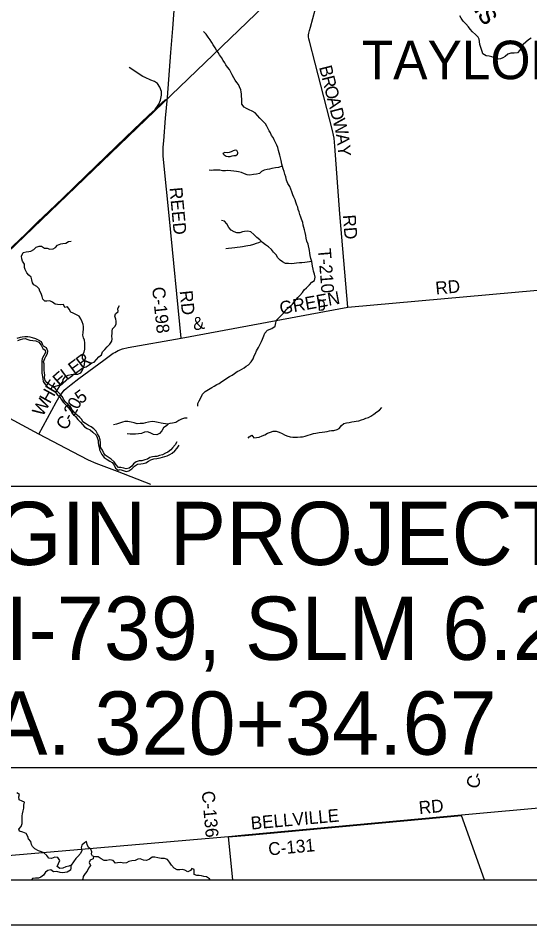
# Model space of a CAD drawing. Extents: x 0 to 34, y 0 to 22.
# Drawn here: x 5.532 to 6.665, y 14 to 16.008 of the extents above; entities that cross this region are included whole.
import ezdxf

# ---------------------------------------------------------------- set-up
doc = ezdxf.new("R2010")
doc.units = 0
for name, color, linetype in [('GM_X_Corporation', 7, 'Continuous'), ('GM_X_County_Road', 7, 'Continuous'), ('GM_X_County_Road_Text', 7, 'Continuous'), ('GM_X_Minor_Lake', 7, 'Continuous'), ('GM_X_Minor_River', 7, 'Continuous'), ('GM_X_Minor_River_Text', 7, 'Continuous'), ('GM_X_Rail_Line', 7, 'Continuous'), ('GM_X_Township_Road', 7, 'Continuous'), ('GM_X_Township_Road_Text', 7, 'Continuous'), ('GM_X_Township_Text', 7, 'Continuous'), ('SH_Data', 7, 'Continuous'), ('SH_Text', 7, 'Continuous')]:
    doc.layers.add(name, color=color, linetype=linetype)

msp = doc.modelspace()

# ---------------------------------------------------------------- linework, layer by layer
at = {"layer": 'GM_X_Corporation'}
msp.add_lwpolyline([(2.7052, 14.1), (8.9, 14.1), (8.9, 20.9), (3.3687, 20.9)], dxfattribs=at)
msp.add_lwpolyline([(5.0367, 14.1), (8.579, 14.1), (8.5781, 14.1185), (8.5553, 14.4065), (8.4217, 14.3956), (8.2117, 14.3797), (8.0986, 14.3711), (7.9912, 14.363), (7.8543, 14.3535), (7.661, 14.3447), (7.5929, 14.3405), (7.4631, 14.3291), (7.1407, 14.2995), (6.5134, 14.2426), (6.0344, 14.1984), (5.9982, 14.195), (5.4229, 14.1455), (5.0357, 14.1114)], close=True, dxfattribs=at)
at = {"layer": 'GM_X_County_Road'}
for p, q in [((6.5647, 14.1), (6.5135, 14.2423)), ((6.0076, 14.1), (5.9983, 14.1947))]:
    msp.add_line(p, q, dxfattribs=at)
for points in [[(5.8932, 15.2994), (5.8674, 15.5635), (5.855, 15.6874), (5.8535, 15.703), (5.8532, 15.7217), (5.8547, 15.7358), (5.8584, 15.7865), (5.8627, 15.8321), (5.8703, 15.9318), (5.8747, 15.985), (5.8831, 16.0962)], [(5.746, 15.2677), (5.7539, 15.2718), (5.7631, 15.2753), (5.7762, 15.2782), (5.8932, 15.2994), (6.2619, 15.3675), (6.888, 15.4237)], [(5.5784, 15.0868), (5.6166, 15.1573), (5.6223, 15.1676), (5.6342, 15.1836), (5.6386, 15.1878), (5.6496, 15.1967), (5.6669, 15.2098), (5.7217, 15.2506), (5.7425, 15.2659), (5.746, 15.2677)], [(5.826, 14.9751), (5.7525, 15.0039), (5.7051, 15.0219), (5.6884, 15.0289), (5.6697, 15.0384), (5.5784, 15.0868), (5.4856, 15.1361)], [(5.9983, 14.1947), (6.0345, 14.1981), (6.5135, 14.2423)]]:
    msp.add_lwpolyline(points, dxfattribs=at)
at = {"layer": 'GM_X_Minor_Lake'}
for points in [[(6.0184, 15.709), (6.0188, 15.7104), (6.0165, 15.7146), (6.0125, 15.7156), (6.008, 15.7139), (6.0036, 15.712), (5.9996, 15.7103), (5.9947, 15.7094), (5.9902, 15.7099), (5.9851, 15.7079)], [(5.9851, 15.7079), (5.9886, 15.7048), (5.9928, 15.7018), (5.9975, 15.701), (6.0013, 15.7016), (6.0057, 15.7027), (6.0098, 15.7032), (6.014, 15.7032), (6.0176, 15.7064), (6.0184, 15.709)], [(6.1979, 15.3842), (6.1989, 15.3785), (6.1987, 15.3736), (6.1986, 15.3694), (6.1984, 15.3652), (6.1988, 15.3614), (6.2034, 15.3616), (6.2073, 15.362), (6.2092, 15.3637)], [(6.2092, 15.3637), (6.2104, 15.3648), (6.2106, 15.3695), (6.2104, 15.3739), (6.2095, 15.3783), (6.2061, 15.3819), (6.2017, 15.3829), (6.1979, 15.3842)]]:
    msp.add_lwpolyline(points, dxfattribs=at)
at = {"layer": 'GM_X_Minor_River'}
for points in [[(6.5566, 15.943), (6.5544, 15.9494), (6.5537, 15.9563), (6.5529, 15.961), (6.5503, 15.9659), (6.5446, 15.9717), (6.5382, 15.977), (6.5327, 15.9835), (6.5292, 15.9884), (6.5233, 15.9953), (6.5173, 16.0013), (6.5128, 16.0076), (6.5103, 16.0129)], [(6.1087, 15.7144), (6.1074, 15.7212), (6.1053, 15.7262), (6.1029, 15.7311), (6.0991, 15.7384), (6.0965, 15.7431), (6.0935, 15.7481), (6.0911, 15.7534), (6.0883, 15.7583), (6.0849, 15.7639), (6.0828, 15.7686), (6.08, 15.7734), (6.074, 15.7797), (6.0674, 15.786), (6.0621, 15.7922), (6.0567, 15.7981), (6.0504, 15.802), (6.0438, 15.805), (6.0376, 15.8075), (6.0325, 15.8102), (6.0276, 15.8169), (6.0273, 15.8235), (6.0271, 15.8292), (6.0268, 15.8343), (6.0266, 15.8395), (6.0262, 15.8444), (6.0249, 15.8492), (6.0221, 15.8558), (6.0199, 15.8607), (6.0165, 15.8655), (6.0126, 15.8707), (6.0097, 15.8754), (6.0062, 15.8823), (6.003, 15.888), (5.9998, 15.8939), (5.9961, 15.8992), (5.9923, 15.904), (5.9895, 15.9089), (5.9863, 15.914), (5.9823, 15.9203), (5.978, 15.9268), (5.9748, 15.9315), (5.9716, 15.9367), (5.9683, 15.9416), (5.9641, 15.9485), (5.9613, 15.9534), (5.9572, 15.9599), (5.953, 15.9652), (5.9482, 15.9721), (5.9429, 15.9784)], [(6.6679, 15.9632), (6.662, 15.9595), (6.6559, 15.9542), (6.6502, 15.9496), (6.6462, 15.9428), (6.6426, 15.9366), (6.6373, 15.9309), (6.6303, 15.93), (6.6229, 15.9304), (6.6164, 15.9278), (6.61, 15.923), (6.605, 15.92), (6.5997, 15.9174), (6.595, 15.9168), (6.5882, 15.9193), (6.5812, 15.9222), (6.5747, 15.9234), (6.5681, 15.9243), (6.5611, 15.9285), (6.5591, 15.9335), (6.5579, 15.9382), (6.5566, 15.943)], [(5.9297, 15.1483), (5.9298, 15.1542), (5.9328, 15.1606), (5.9366, 15.1669), (5.9405, 15.1752), (5.9466, 15.181), (5.9538, 15.1854), (5.961, 15.1901), (5.9661, 15.1931), (5.9718, 15.1965), (5.977, 15.1989), (5.9831, 15.2034), (5.9889, 15.2066), (5.9945, 15.2104), (6, 15.2143), (6.0059, 15.2173), (6.0114, 15.2207), (6.0169, 15.2251), (6.0224, 15.2273), (6.0271, 15.2301), (6.0323, 15.2337), (6.0372, 15.2369), (6.0423, 15.2401), (6.048, 15.2465), (6.0523, 15.2535), (6.0551, 15.2599), (6.0574, 15.2651), (6.0601, 15.2707), (6.0645, 15.2783), (6.0672, 15.2842), (6.0712, 15.2914), (6.0729, 15.2968), (6.076, 15.3039), (6.0787, 15.3101), (6.0846, 15.3169), (6.0941, 15.3206), (6.1013, 15.3255), (6.1029, 15.3329), (6.104, 15.3388), (6.1086, 15.3437), (6.1143, 15.3494), (6.121, 15.3562), (6.1255, 15.3618), (6.1322, 15.3677), (6.1394, 15.3745), (6.1448, 15.3807), (6.1511, 15.3888), (6.156, 15.3937), (6.1615, 15.4005), (6.1657, 15.406), (6.1705, 15.4107), (6.177, 15.4175), (6.1821, 15.423), (6.1886, 15.4271), (6.1901, 15.4342), (6.1883, 15.441), (6.1864, 15.4471), (6.1851, 15.452), (6.184, 15.4587), (6.1831, 15.464), (6.1824, 15.4687), (6.1805, 15.4756), (6.179, 15.482), (6.1781, 15.4872), (6.177, 15.4932), (6.174, 15.5069), (6.1714, 15.5137), (6.1697, 15.5202), (6.169, 15.5267), (6.1679, 15.5329), (6.1662, 15.539), (6.165, 15.5441), (6.1633, 15.5496), (6.1622, 15.555), (6.1596, 15.5626), (6.1581, 15.5673), (6.1562, 15.5728), (6.1541, 15.5785), (6.1523, 15.5839), (6.1512, 15.5888), (6.1491, 15.5939), (6.1471, 15.6004), (6.1456, 15.6055), (6.1428, 15.6114), (6.1407, 15.6165), (6.1379, 15.623), (6.136, 15.6287), (6.1336, 15.6348), (6.1295, 15.6416), (6.1267, 15.6489), (6.1246, 15.6561), (6.1228, 15.6622), (6.1211, 15.6681), (6.1191, 15.6743), (6.1172, 15.6795), (6.1159, 15.6842), (6.1142, 15.6922), (6.1131, 15.6983), (6.1116, 15.7041), (6.1102, 15.7095), (6.1087, 15.7144)], [(6.117, 15.6801), (6.1087, 15.6772), (6.1018, 15.6761), (6.0937, 15.6745), (6.0889, 15.6735), (6.0834, 15.6726), (6.0772, 15.6713), (6.0713, 15.6681), (6.0665, 15.664), (6.0601, 15.6623), (6.0535, 15.6612), (6.0455, 15.6597), (6.0396, 15.6609), (6.033, 15.6632), (6.0266, 15.6659), (6.0204, 15.6676), (6.0154, 15.6679), (6.0099, 15.6686), (6.0033, 15.6698), (5.9965, 15.6704), (5.9916, 15.6699), (5.9849, 15.6699), (5.9785, 15.6711), (5.9719, 15.6713), (5.9651, 15.6708), (5.9603, 15.6706), (5.9552, 15.671)], [(6.1823, 15.469), (6.1723, 15.4676), (6.1666, 15.4669), (6.1602, 15.4662), (6.1553, 15.4658), (6.1486, 15.4651), (6.1431, 15.4644), (6.1373, 15.464), (6.1308, 15.4641), (6.124, 15.4647), (6.1174, 15.4681), (6.1123, 15.4718), (6.1074, 15.4773), (6.1035, 15.4838), (6.0978, 15.4895), (6.0931, 15.4952), (6.0863, 15.5013), (6.0797, 15.5061), (6.0733, 15.5112), (6.0671, 15.5166), (6.0607, 15.5223), (6.0541, 15.5286), (6.0473, 15.5345), (6.0409, 15.5363), (6.0337, 15.5355), (6.0289, 15.5344), (6.0232, 15.5322), (6.0164, 15.532), (6.0104, 15.5347), (6.0041, 15.5385), (5.9985, 15.5444), (5.9944, 15.5519), (5.9889, 15.558), (5.9827, 15.5599)], [(5.6087, 15.1922), (5.615, 15.1928), (5.6199, 15.1941), (5.6262, 15.1968), (5.631, 15.2022), (5.6321, 15.2072), (5.6363, 15.2138), (5.6432, 15.2174), (5.6496, 15.2188), (5.6543, 15.219), (5.6598, 15.219), (5.6646, 15.2197), (5.671, 15.2225), (5.6747, 15.228), (5.677, 15.2342), (5.6795, 15.2407), (5.6799, 15.2471), (5.675, 15.254), (5.6745, 15.2612), (5.6781, 15.2684), (5.68, 15.2745), (5.6802, 15.2792), (5.6803, 15.2841), (5.6801, 15.2889), (5.6792, 15.2946), (5.6771, 15.2999), (5.6758, 15.3058), (5.6759, 15.3117), (5.6772, 15.3196), (5.6769, 15.3247), (5.676, 15.3297), (5.6741, 15.3356), (5.6711, 15.3418), (5.6671, 15.3479), (5.6603, 15.3514), (5.6539, 15.3543), (5.649, 15.3568), (5.6456, 15.3634), (5.6417, 15.3686), (5.6354, 15.3671), (5.6326, 15.3734), (5.6262, 15.3732), (5.6196, 15.3736), (5.6144, 15.374), (5.608, 15.3788), (5.6024, 15.3819), (5.5959, 15.3813), (5.5912, 15.3808), (5.5867, 15.3857), (5.5854, 15.3911), (5.5831, 15.3981), (5.5805, 15.4032), (5.579, 15.4082), (5.5735, 15.4133), (5.5669, 15.4168), (5.5641, 15.4215), (5.5623, 15.4282), (5.5612, 15.4344), (5.5563, 15.4386), (5.5514, 15.444), (5.5478, 15.451), (5.5467, 15.4558), (5.5467, 15.4632), (5.5422, 15.4696), (5.5402, 15.4744), (5.5394, 15.481), (5.5436, 15.4884), (5.5503, 15.4905), (5.5558, 15.4908), (5.5605, 15.4919), (5.5668, 15.4957), (5.5719, 15.5002), (5.5789, 15.503), (5.5842, 15.503), (5.5905, 15.498), (5.5967, 15.4982), (5.6028, 15.4961), (5.61, 15.4966), (5.6147, 15.5), (5.6197, 15.5051), (5.6265, 15.5077), (5.6314, 15.5084), (5.6377, 15.5097), (5.644, 15.5129), (5.6498, 15.5142)], [(6.0712, 15.5131), (6.0642, 15.5105), (6.0591, 15.5088), (6.053, 15.5064), (6.0458, 15.5045), (6.0411, 15.5036), (6.0363, 15.5029), (6.0291, 15.5014), (6.0236, 15.5009), (6.0168, 15.4998), (6.0121, 15.4992), (6.0051, 15.4983), (5.998, 15.4976), (5.9922, 15.4972)], [(5.677, 15.2342), (5.6828, 15.2354), (5.6893, 15.2401), (5.6956, 15.2442), (5.7003, 15.2457), (5.7055, 15.2521), (5.7108, 15.2574), (5.7169, 15.2623), (5.7192, 15.2687), (5.7243, 15.274), (5.7293, 15.2799), (5.7352, 15.2857), (5.7396, 15.2924), (5.7406, 15.2973), (5.7396, 15.3034), (5.7408, 15.31), (5.7408, 15.3147), (5.7414, 15.3195), (5.746, 15.3248), (5.7492, 15.3302), (5.7495, 15.3367), (5.7482, 15.3414), (5.7461, 15.3477), (5.7479, 15.3528), (5.7534, 15.3579), (5.7532, 15.3646), (5.7567, 15.3712)], [(5.8839, 15.0696), (5.8797, 15.063), (5.874, 15.0566), (5.8701, 15.0517), (5.8633, 15.0468), (5.8585, 15.0443), (5.8517, 15.0411), (5.8455, 15.0391), (5.8394, 15.0374), (5.8346, 15.0369), (5.8299, 15.0365), (5.8235, 15.0345), (5.8185, 15.0313), (5.8126, 15.0294), (5.806, 15.0277), (5.8001, 15.0276), (5.7937, 15.0249), (5.7876, 15.0208), (5.784, 15.0159), (5.7779, 15.011), (5.7711, 15.0097), (5.766, 15.0114), (5.7599, 15.0128), (5.7542, 15.0128), (5.7495, 15.0187), (5.7448, 15.0254), (5.7382, 15.0313), (5.7316, 15.0355), (5.7252, 15.0397), (5.7212, 15.046), (5.7188, 15.051), (5.7152, 15.0561), (5.7147, 15.0608), (5.7145, 15.0675), (5.7142, 15.0739), (5.7116, 15.081), (5.7082, 15.0876), (5.7052, 15.0928), (5.6999, 15.0985), (5.6937, 15.1025), (5.6877, 15.1059), (5.6814, 15.1098), (5.6758, 15.114), (5.673, 15.1187), (5.6688, 15.1235), (5.6632, 15.1288), (5.6573, 15.1344), (5.652, 15.1403), (5.6483, 15.1452), (5.643, 15.1523), (5.6368, 15.1572), (5.633, 15.1641), (5.6304, 15.1692), (5.6253, 15.1753), (5.6197, 15.1807), (5.6148, 15.1871), (5.6088, 15.1921), (5.6021, 15.1958), (5.5961, 15.2007), (5.5925, 15.2055), (5.5905, 15.2123), (5.5911, 15.2171), (5.5905, 15.2222), (5.5896, 15.2279), (5.5898, 15.2341), (5.5899, 15.2423), (5.5888, 15.247), (5.5915, 15.2537), (5.5939, 15.2586), (5.5974, 15.2652), (5.598, 15.2705), (5.5948, 15.2774), (5.5888, 15.281), (5.5861, 15.2861), (5.5841, 15.2913), (5.5777, 15.2949), (5.5714, 15.2978), (5.5644, 15.2999), (5.5593, 15.3011), (5.5535, 15.3019), (5.5474, 15.3021), (5.5413, 15.3012), (5.5366, 15.3006), (5.5296, 15.2984)], [(5.5316, 15.2936), (5.5377, 15.2964), (5.5424, 15.2974), (5.5478, 15.2981), (5.5536, 15.2962), (5.5585, 15.2948), (5.5652, 15.2938), (5.5714, 15.293), (5.5778, 15.2905), (5.5833, 15.2839), (5.5867, 15.2763), (5.5921, 15.2728), (5.5929, 15.2673), (5.589, 15.2605), (5.5858, 15.2537), (5.5848, 15.2488), (5.5846, 15.2435), (5.5844, 15.2364), (5.5847, 15.2262), (5.5849, 15.2213), (5.586, 15.2142), (5.5869, 15.2093), (5.588, 15.2034), (5.5908, 15.1987), (5.5961, 15.1924), (5.6019, 15.1882), (5.6078, 15.1838), (5.6138, 15.1813), (5.6189, 15.1746), (5.6245, 15.1691), (5.6275, 15.1641), (5.6319, 15.1573), (5.6387, 15.1508), (5.6441, 15.1445), (5.6488, 15.1384), (5.6529, 15.1319), (5.659, 15.1253), (5.6646, 15.1193), (5.6701, 15.1134), (5.6748, 15.1077), (5.6793, 15.103), (5.6852, 15.0987), (5.692, 15.0964), (5.6978, 15.0909), (5.7048, 15.0842), (5.7076, 15.0791), (5.7093, 15.0728), (5.7098, 15.0679), (5.7105, 15.0631), (5.7115, 15.0578), (5.7126, 15.0521), (5.7152, 15.0462), (5.7178, 15.0413), (5.7225, 15.0348), (5.7291, 15.0304), (5.7352, 15.0268), (5.7401, 15.0241), (5.7446, 15.018), (5.7476, 15.011), (5.7536, 15.0071), (5.7584, 15.0081), (5.7648, 15.0061), (5.7714, 15.0038), (5.7777, 15.0053), (5.7841, 15.0094), (5.7898, 15.0153), (5.7965, 15.0202), (5.8041, 15.0209), (5.8094, 15.0214), (5.8147, 15.0229), (5.8211, 15.0269), (5.8263, 15.0295), (5.8329, 15.0318), (5.8395, 15.033), (5.8468, 15.0343), (5.8515, 15.0353), (5.857, 15.0369), (5.8623, 15.0384), (5.8684, 15.0418), (5.8733, 15.0444), (5.879, 15.0497), (5.8842, 15.0556), (5.8884, 15.0624)], [(6.0412, 15.0778), (6.0436, 15.0803), (6.0497, 15.0841), (6.0538, 15.0786), (6.0602, 15.0789), (6.0656, 15.0797), (6.0726, 15.0826), (6.0785, 15.0851), (6.0842, 15.0887), (6.0908, 15.0913), (6.0971, 15.0928), (6.1035, 15.0929), (6.1101, 15.091), (6.1171, 15.0883), (6.1222, 15.0852), (6.1273, 15.0831), (6.1341, 15.0808), (6.14, 15.08), (6.1455, 15.08), (6.1508, 15.0801), (6.157, 15.0803), (6.162, 15.0808), (6.1678, 15.0823), (6.1741, 15.0844), (6.1798, 15.0861), (6.1864, 15.0877), (6.1916, 15.0888), (6.1989, 15.0901), (6.205, 15.091), (6.2109, 15.0918), (6.2162, 15.0925), (6.2215, 15.0936), (6.2262, 15.0943), (6.2314, 15.0949), (6.2382, 15.0966), (6.2431, 15.0994), (6.2481, 15.106), (6.2534, 15.1098), (6.2595, 15.1114), (6.2648, 15.1122), (6.2709, 15.114), (6.276, 15.1148), (6.2807, 15.1153), (6.2862, 15.1158), (6.2925, 15.1179), (6.2972, 15.12), (6.3021, 15.122), (6.308, 15.1235), (6.3133, 15.1261), (6.32, 15.1308), (6.3263, 15.1357), (6.3324, 15.1399), (6.3373, 15.1457)], [(5.9065, 15.1223), (5.9006, 15.1221), (5.8942, 15.1196), (5.8881, 15.1166), (5.8814, 15.1127), (5.8742, 15.1105), (5.868, 15.1099), (5.8632, 15.109), (5.8492, 15.1106), (5.842, 15.1123), (5.8352, 15.1135), (5.829, 15.1147), (5.8208, 15.1134), (5.8144, 15.1115), (5.8087, 15.1102), (5.8023, 15.1099), (5.7956, 15.1097), (5.7892, 15.1113), (5.7828, 15.113), (5.7754, 15.1142), (5.7684, 15.1142), (5.7631, 15.1131), (5.7564, 15.1107), (5.7504, 15.1083), (5.7435, 15.1074)], [(5.8651, 15.1094), (5.8611, 15.1058), (5.8543, 15.1007), (5.8505, 15.0941), (5.8455, 15.0882), (5.8391, 15.0847), (5.8319, 15.086), (5.8245, 15.0895), (5.8183, 15.0914), (5.812, 15.0909), (5.8052, 15.0882), (5.7991, 15.087), (5.7921, 15.0868), (5.7855, 15.0863), (5.7804, 15.0863), (5.7735, 15.0873)], [(5.5338, 14.2122), (5.5389, 14.2178), (5.541, 14.2245), (5.5411, 14.2364), (5.5415, 14.2411), (5.5423, 14.2459), (5.5438, 14.2525), (5.5446, 14.2582), (5.5452, 14.2652), (5.5464, 14.2717), (5.5415, 14.2741), (5.5349, 14.2768), (5.534, 14.2835), (5.5351, 14.2886), (5.5291, 14.2926)], [(5.9574, 14.1), (5.9557, 14.1019), (5.9494, 14.1065), (5.943, 14.1073), (5.9379, 14.1086), (5.933, 14.1092), (5.9279, 14.1094), (5.9216, 14.1112), (5.9218, 14.118), (5.9221, 14.1229), (5.9171, 14.125), (5.9141, 14.1201), (5.9078, 14.1171), (5.901, 14.121), (5.8952, 14.1223), (5.8899, 14.1222), (5.884, 14.1218), (5.8774, 14.1256), (5.8719, 14.1321), (5.8674, 14.1388), (5.8627, 14.1451), (5.8561, 14.147), (5.8489, 14.1472), (5.8417, 14.1484), (5.8351, 14.1498), (5.8292, 14.1498), (5.8231, 14.1458), (5.8167, 14.1428), (5.8095, 14.1436), (5.8021, 14.1465), (5.7974, 14.1456), (5.7911, 14.1424), (5.7843, 14.1421), (5.7771, 14.1404), (5.7723, 14.1372), (5.7659, 14.1363), (5.7589, 14.1378), (5.7526, 14.1375), (5.7479, 14.1369), (5.7423, 14.1425), (5.7351, 14.1438), (5.729, 14.1427), (5.7231, 14.1427), (5.7163, 14.1464), (5.7097, 14.1508), (5.7033, 14.151), (5.697, 14.152), (5.6948, 14.1569), (5.6958, 14.1617), (5.6932, 14.1679), (5.6883, 14.171), (5.6853, 14.1778), (5.6838, 14.1845), (5.679, 14.1813), (5.6735, 14.1766), (5.6716, 14.1705), (5.6733, 14.1646), (5.67, 14.1582), (5.6647, 14.1516), (5.6599, 14.1469), (5.6547, 14.1393), (5.6496, 14.1325), (5.6448, 14.1297), (5.638, 14.1288), (5.631, 14.1254), (5.6246, 14.125), (5.6185, 14.1292), (5.6218, 14.1361), (5.6245, 14.1427), (5.6203, 14.149), (5.6135, 14.1497), (5.6065, 14.1469), (5.6003, 14.1477), (5.5957, 14.1536), (5.5895, 14.1594), (5.5839, 14.1618), (5.5771, 14.1642), (5.5695, 14.1682), (5.5642, 14.1733), (5.5622, 14.1781), (5.5601, 14.1845), (5.5554, 14.1906), (5.5536, 14.1959), (5.55, 14.2022), (5.5424, 14.2053), (5.5356, 14.2074), (5.5338, 14.2122)], [(5.6991, 14.1517), (5.6983, 14.1463), (5.6919, 14.1429), (5.6894, 14.1378), (5.6922, 14.1313), (5.6884, 14.1253), (5.6851, 14.1189), (5.6804, 14.1138), (5.676, 14.1073), (5.6757, 14.1022), (5.6748, 14.1)], [(5.6488, 14.132), (5.6488, 14.1261), (5.648, 14.1211), (5.6412, 14.1168), (5.6355, 14.1159), (5.6302, 14.1153), (5.6253, 14.1159), (5.6179, 14.1181), (5.6109, 14.1173), (5.6047, 14.1215), (5.5982, 14.1204), (5.5929, 14.117), (5.5881, 14.1104), (5.5822, 14.1053), (5.5773, 14.1037), (5.5705, 14.1031), (5.564, 14.1024), (5.5619, 14.1)]]:
    msp.add_lwpolyline(points, dxfattribs=at)
at = {"layer": 'GM_X_Rail_Line'}
for points in [[(5.2658, 15.2105), (5.3357, 15.2914), (5.4094, 15.3777), (5.4899, 15.4707), (5.6406, 15.6155), (5.8342, 15.8017), (6.1881, 16.1426), (6.4582, 16.4022), (6.7352, 16.6681), (7.0136, 16.9364), (7.2435, 17.1561), (7.4421, 17.3509), (7.6263, 17.5265), (7.9296, 17.8183), (8.0773, 17.9623), (8.4366, 18.3089), (8.7009, 18.5622), (8.9, 18.7553)], [(5.8353, 15.8057), (5.8436, 15.8171), (5.8475, 15.8264), (5.8499, 15.8373), (5.8494, 15.8456), (5.846, 15.8547), (5.8405, 15.8626), (5.8339, 15.8674), (5.8257, 15.8707), (5.8136, 15.8762), (5.8083, 15.8787), (5.7784, 15.8983)], [(5.8353, 15.8057), (5.8403, 15.8103), (5.8585, 15.8273)], [(5.1791, 15.2007), (5.1876, 15.1924), (5.1929, 15.1896), (5.2017, 15.1852), (5.2089, 15.1836), (5.2189, 15.1829), (5.2298, 15.1853), (5.2378, 15.1885), (5.2471, 15.1938), (5.2553, 15.2008), (5.304, 15.2562), (5.3542, 15.3146), (5.4385, 15.4124), (5.4892, 15.4703), (5.5023, 15.4843), (5.5215, 15.5033), (5.5491, 15.5304), (5.5753, 15.5559), (5.6009, 15.5805), (5.6314, 15.6092), (5.6821, 15.6582), (5.7707, 15.7438), (5.8219, 15.7932), (5.8353, 15.8057)]]:
    msp.add_lwpolyline(points, dxfattribs=at)
at = {"layer": 'GM_X_Township_Road'}
msp.add_lwpolyline([(6.2619, 15.3675), (6.2445, 15.5747), (6.2334, 15.724), (6.2316, 15.7419), (6.2303, 15.7488), (6.2278, 15.7592), (6.1897, 15.9077), (6.1773, 15.9565), (6.1759, 15.9621), (6.1753, 15.9661), (6.1754, 15.9704), (6.176, 15.9741), (6.1776, 15.9806), (6.1794, 15.9875), (6.2056, 16.0841), (6.2073, 16.0906), (6.2075, 16.0921)], dxfattribs=at)
at = {"layer": 'SH_Data'}
for p, q in [((2.1, 14.1), (8.9, 14.1)), ((2, 14), (9, 14))]:
    msp.add_line(p, q, dxfattribs=at)
at = {"layer": 'SH_Text'}
msp.add_lwpolyline([(5.1971, 14.9716), (7.0199, 14.9716), (7.0199, 14.3479), (5.1971, 14.3479)], close=True, dxfattribs=at)

# ---------------------------------------------------------------- texts
at = {"layer": 'GM_X_County_Road_Text'}
for s, height, rotation, p in [('REED', 0.02841, 275.266, (5.8673, 15.632)), ('RD', 0.02841, 5.4177, (6.4572, 15.3955)), ('C-198', 0.02841, 276.0675, (5.8287, 15.4112)), ('RD', 0.02841, 275.9068, (5.8898, 15.4034)), ('GREEN', 0.02841, 10.3416, (6.1137, 15.3512)), ('&', 0.0284, 10.6168, (5.9216, 15.3158)), ('R', 0.0284, 36.6487, (5.6736, 15.2298)), ('E', 0.0284, 36.6428, (5.6565, 15.2171)), ('E', 0.0284, 41.4492, (5.6241, 15.1907)), ('L', 0.0284, 36.7653, (5.6395, 15.2044)), ('E', 0.0284, 59.2626, (5.6147, 15.1743)), ('H', 0.0284, 60.9514, (5.6027, 15.1526)), ('5', 0.0284, 35.727, (5.6707, 15.1524)), ('W', 0.0284, 60.9881, (5.5867, 15.1238)), ('0', 0.0284, 61.6086, (5.6646, 15.1395)), ('2', 0.0284, 61.1754, (5.656, 15.124)), ('C', 0.0284, 61.1164, (5.6391, 15.0933)), ('-', 0.0284, 61.1245, (5.6504, 15.1137)), ('-', 0.0284, 68.8437, (6.5566, 14.3207)), ('C', 0.0284, 70.8936, (6.5491, 14.2989)), ('C-136', 0.02841, 275.2447, (5.9386, 14.2953)), ('RD', 0.02841, 5.4159, (6.4205, 14.2451)), ('BELLVILLE', 0.02841, 5.2407, (6.0484, 14.2109)), ('C-131', 0.02841, 5.2446, (6.0873, 14.1536))]:
    msp.add_text(s, height=height, rotation=rotation, dxfattribs=at).set_placement(p)
at = {"layer": 'GM_X_Minor_River_Text'}
msp.add_text('Willis', height=0.04735, rotation=305.6442, dxfattribs=at).set_placement((6.4802, 16.1088))
at = {"layer": 'GM_X_Township_Road_Text'}
for s, height, rotation, p in [('B', 0.0284, 284.2152, (6.1982, 15.8992)), ('R', 0.0284, 284.2114, (6.2039, 15.8766)), ('O', 0.0284, 284.2156, (6.2097, 15.854)), ('A', 0.0284, 284.2138, (6.2158, 15.8297)), ('D', 0.0284, 284.212, (6.2219, 15.8055)), ('W', 0.0284, 284.0597, (6.2281, 15.7813)), ('A', 0.0284, 277.0667, (6.2359, 15.7503)), ('Y', 0.0284, 275.0592, (6.239, 15.7257)), ('RD', 0.02841, 274.4359, (6.251, 15.5715)), ('T-210', 0.02841, 274.5074, (6.1961, 15.4967))]:
    msp.add_text(s, height=height, rotation=rotation, dxfattribs=at).set_placement(p)
at = {"layer": 'GM_X_Township_Text'}
msp.add_text('TAYLOR', height=0.08523, rotation=0, dxfattribs=at).set_placement((6.2928, 15.8725))
at = {"layer": 'SH_Text'}
for s, p in [('BEGIN PROJECT  ', (5.2331, 14.7968)), ('UNI-739, SLM 6.21 ', (5.2331, 14.5868)), ('STA. 320+34.67      ', (5.2331, 14.3768))]:
    msp.add_text(s, height=0.14, dxfattribs=at).set_placement(p)

doc.saveas('drawing.dxf')
